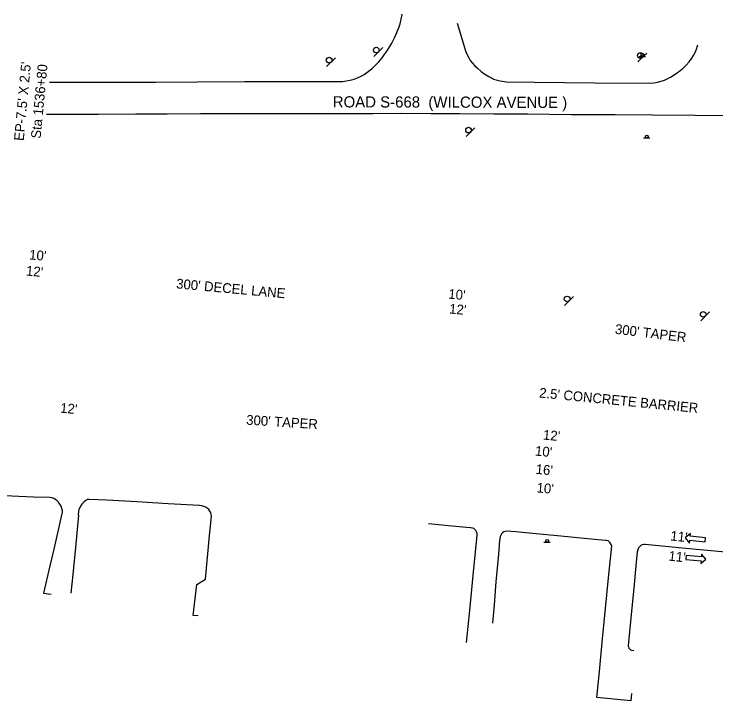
# Model space of a CAD drawing. Extents: x 1800374 to 1802004, y 1187708 to 1188617.
# Drawn here: x 1801167 to 1801669, y 1187839 to 1188331 of the extents above; entities that cross this region are included whole.
import ezdxf

# ---------------------------------------------------------------- set-up
doc = ezdxf.new("R2010")
doc.units = 0
for name, color, linetype in [('RD_EX_Road', 7, 'Continuous'), ('RD_PD_Final_LnLine', 7, 'Continuous'), ('RD_PD_Final_TX', 7, 'Continuous'), ('RD_TX_RoadID', 7, 'Continuous'), ('SN_P_Signs', 7, 'Continuous')]:
    doc.layers.add(name, color=color, linetype=linetype)

# ---------------------------------------------------------------- blocks, each defined once
blk = doc.blocks.new('SARRW2')
at = {"layer": 'RD_PD_Final_LnLine'}
blk.add_lwpolyline([(-12, 1.2), (-12, -1.2), (-2.83, -1.2), (-2.83, -2.83), (0, 0), (-2.83, 2.83), (-2.83, 1.2)], close=True, dxfattribs=at)

msp = doc.modelspace()

# ---------------------------------------------------------------- linework, layer by layer
at = {"layer": 'RD_EX_Road'}
for points in [[(1801192.42, 1188282.25), (1801206.31, 1188282.18), (1801232.85, 1188282.21), (1801268.14, 1188282.24), (1801297.93, 1188282.47), (1801331.99, 1188282.57), (1801366.64, 1188282.73), (1801401.99, 1188282.76), (1801404.75, 1188283.05), (1801407.47, 1188283.57), (1801410.13, 1188284.32), (1801412.72, 1188285.3), (1801415.22, 1188286.49), (1801417.41, 1188287.76), (1801420.28, 1188289.76), (1801423.01, 1188291.94), (1801425.58, 1188294.3), (1801427.99, 1188296.84), (1801430.23, 1188299.53), (1801432.27, 1188302.36), (1801432.65, 1188302.94), (1801435, 1188306.46), (1801437.14, 1188310.11), (1801439.08, 1188313.87), (1801440.81, 1188317.73), (1801442.31, 1188321.68), (1801443.08, 1188324), (1801443.96, 1188327.31), (1801444.61, 1188330.67), (1801444.65, 1188330.92)], [(1801483.98, 1188324.49), (1801489.84, 1188304.69), (1801490.78, 1188302.28), (1801491.93, 1188299.96), (1801493.29, 1188297.76), (1801494.85, 1188295.69), (1801496.59, 1188293.77), (1801498.41, 1188292.09), (1801501.01, 1188289.92), (1801503.75, 1188287.94), (1801506.62, 1188286.15), (1801509.62, 1188284.56), (1801509.89, 1188284.43), (1801514.61, 1188283.24), (1801518.85, 1188282.37), (1801539.13, 1188282.19), (1801582.15, 1188281.81), (1801621.82, 1188281.57), (1801624.47, 1188281.75), (1801627.09, 1188282.15), (1801629.66, 1188282.79), (1801632.16, 1188283.66), (1801634.58, 1188284.75), (1801636.89, 1188286.05), (1801637.9, 1188286.71), (1801640.57, 1188288.35), (1801643.09, 1188290.18), (1801645.48, 1188292.21), (1801647.7, 1188294.4), (1801649.75, 1188296.76), (1801651.61, 1188299.27), (1801652.9, 1188301.27), (1801654.07, 1188303.5), (1801655.02, 1188305.83), (1801655.75, 1188308.24), (1801655.87, 1188308.84)], [(1801750.18, 1188257.47), (1801742.16, 1188257.54), (1801712.17, 1188257.84), (1801684.43, 1188258.15), (1801653.76, 1188258.34), (1801623.47, 1188258.55), (1801596.82, 1188258.7), (1801565.74, 1188258.88), (1801534.34, 1188259.2), (1801510.07, 1188259.36), (1801485.44, 1188259.54), (1801465.11, 1188259.51), (1801443.43, 1188259.67), (1801423.7, 1188259.6), (1801400.14, 1188259.52), (1801374.88, 1188259.49), (1801351.57, 1188259.44), (1801326.73, 1188259.43), (1801300.32, 1188259.52), (1801276.46, 1188259.35), (1801254.13, 1188259.2), (1801227.4, 1188259.14), (1801201, 1188258.95), (1801190.24, 1188258.95)], [(1801201.74, 1187973.73), (1801201.61, 1187975.46), (1801201.23, 1187977.16), (1801200.63, 1187978.8), (1801199.82, 1187980.34), (1801198.89, 1187981.64), (1801197.88, 1187982.69), (1801196.72, 1187983.57), (1801195.43, 1187984.24), (1801194.04, 1187984.7), (1801192.61, 1187984.93), (1801192.55, 1187984.93), (1801181.04, 1187985.29), (1801154.7, 1187986.38), (1801125.59, 1187987.61), (1801124.16, 1187987.2), (1801122.83, 1187986.58), (1801121.6, 1187985.74), (1801120.53, 1187984.73), (1801119.67, 1187983.62), (1801118.69, 1187981.78), (1801117.93, 1187979.84), (1801117.55, 1187978.57)], [(1801298.82, 1187900.38), (1801295.15, 1187900.73), (1801297.8, 1187922.8), (1801303.89, 1187926.72), (1801306.79, 1187957.93), (1801308.15, 1187971.67), (1801308.03, 1187972.96), (1801307.68, 1187974.21), (1801307.11, 1187975.37), (1801306.34, 1187976.42), (1801305.41, 1187977.28), (1801304.13, 1187978.09), (1801302.74, 1187978.69), (1801301.28, 1187979.07), (1801299.77, 1187979.21), (1801299.55, 1187979.21), (1801277.24, 1187980.54), (1801254.75, 1187981.88), (1801233.49, 1187983.09), (1801220.68, 1187983.71), (1801219.58, 1187983.5), (1801218.56, 1187983.05), (1801218.37, 1187982.94), (1801216.91, 1187981.74), (1801215.62, 1187980.37), (1801214.51, 1187978.84), (1801214.22, 1187978.36), (1801213.49, 1187976.29), (1801213.2, 1187975.17), (1801212.93, 1187972.5)], [(1801201.25, 1187973.69), (1801198.94, 1187962.85), (1801195.5, 1187948.11), (1801192.68, 1187936.13), (1801188.03, 1187916.6), (1801193.53, 1187915.92)], [(1801207.97, 1187916.51), (1801209.23, 1187929.92), (1801211.14, 1187949.21), (1801213.43, 1187972.45)], [(1801490.61, 1187881.19), (1801492.94, 1187904.22), (1801495.3, 1187929.3), (1801498.28, 1187958.18), (1801498.16, 1187959.31), (1801497.81, 1187960.39), (1801497.25, 1187961.38), (1801496.61, 1187962.11), (1801495.76, 1187962.75), (1801494.78, 1187963.2), (1801493.74, 1187963.42), (1801493.27, 1187963.44), (1801477.77, 1187964.85), (1801463.3, 1187966.18)], [(1801608.48, 1187844.7), (1801607.98, 1187839.47), (1801583.64, 1187842.04), (1801585.54, 1187860.45), (1801587.79, 1187883.84), (1801590, 1187905.55), (1801592.14, 1187927.65), (1801594.39, 1187950.22), (1801593.91, 1187951.41), (1801593.22, 1187952.5), (1801592.34, 1187953.45), (1801592.29, 1187953.49), (1801591.52, 1187954), (1801590.65, 1187954.3), (1801589.84, 1187954.37), (1801576.98, 1187955.55), (1801557.99, 1187957.37), (1801535.44, 1187959.48), (1801525.81, 1187960.4), (1801519.39, 1187960.98), (1801518.31, 1187960.81), (1801517.29, 1187960.42), (1801516.37, 1187959.82), (1801515.61, 1187959.03), (1801515.03, 1187958.1), (1801514.66, 1187957.07), (1801514.64, 1187956.98), (1801514.26, 1187954.25), (1801513.34, 1187944.4), (1801511.46, 1187924.81), (1801510.29, 1187908.14), (1801509.11, 1187895.02)], [(1801675.84, 1187945.99), (1801644.76, 1187948.86), (1801618.39, 1187951.51), (1801617.31, 1187951.49), (1801616.26, 1187951.23), (1801615.3, 1187950.75), (1801614.46, 1187950.08), (1801613.79, 1187949.23), (1801613.66, 1187949.01), (1801612.69, 1187946.27), (1801611.65, 1187936.09), (1801610.28, 1187920.09), (1801608.41, 1187901.33), (1801606.26, 1187878.96), (1801606.36, 1187878.08), (1801606.69, 1187877.26), (1801607.23, 1187876.55), (1801607.93, 1187876.02), (1801608.44, 1187875.78), (1801610.13, 1187875.62)]]:
    msp.add_lwpolyline(points, dxfattribs=at)
at = {"layer": 'SN_P_Signs'}
for p, q in [((1801424.29, 1188300.51), (1801430.66, 1188306.87)), ((1801613.13, 1188296.62), (1801619.49, 1188302.99)), ((1801390.57, 1188293.34), (1801396.93, 1188299.7)), ((1801614.07, 1188300.62), (1801618.57, 1188300.62)), ((1801490.23, 1188243.25), (1801496.59, 1188249.61)), ((1801617.18, 1188242.3), (1801621.68, 1188242.3)), ((1801560.74, 1188122.48), (1801567.1, 1188128.84)), ((1801658.05, 1188111.44), (1801664.41, 1188117.81)), ((1801545.94, 1187953.06), (1801550.44, 1187953.06))]:
    msp.add_line(p, q, dxfattribs=at)
for centre, radius in [((1801426.06, 1188305.13), 2), ((1801614.89, 1188301.25), 2), ((1801616.33, 1188301.63), 1), ((1801392.33, 1188297.97), 2), ((1801491.99, 1188247.87), 2), ((1801619.44, 1188243.31), 1), ((1801562.5, 1188127.11), 2), ((1801659.81, 1188116.07), 2), ((1801548.2, 1187954.07), 1)]:
    msp.add_circle(centre, radius, dxfattribs=at)

# ---------------------------------------------------------------- block references
at = {"layer": 'RD_PD_Final_LnLine'}
for p, xscale, yscale, rotation in [((1801646.95, 1187956.18), 1.2000000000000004, 1.2000000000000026, 174.6556769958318), ((1801661.75, 1187940.88), 1.2000000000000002, 1.2000000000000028, -5.34432300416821)]:
    msp.add_blockref('SARRW2', p, dxfattribs=dict(at, xscale=xscale, yscale=yscale, rotation=rotation))

# ---------------------------------------------------------------- texts
at = {"layer": 'RD_PD_Final_TX'}
for s, rotation, p in [("10'", 354.7642, (1801177.65, 1188155.41)), ("12'", 354.7642, (1801175.38, 1188143.88)), ("300' DECEL LANE", 354.7642, (1801282.76, 1188134.68)), ("10'", 354.7642, (1801477.34, 1188127.36)), ("12'", 354.7642, (1801477.96, 1188116.74)), ("300' TAPER", 353.1553, (1801596.44, 1188102.22)), ("2.5' CONCRETE BARRIER", 354.4074, (1801542.3, 1188056.63)), ("12'", 354.7642, (1801199.82, 1188045.78)), ("300' TAPER", 356.4156, (1801332.92, 1188037.17)), ("12'", 354.7642, (1801545.02, 1188026.5)), ("10'", 354.7642, (1801539.35, 1188015.04)), ("16'", 354.7642, (1801539.83, 1188002.01)), ("10'", 354.7642, (1801540.45, 1187988.72)), ("11'", 353.9512, (1801636.1, 1187954.36)), ("11'", 353.9512, (1801634.75, 1187939.94))]:
    msp.add_text(s, height=7, rotation=rotation, dxfattribs=at).set_placement(p)
at = {"layer": 'RD_TX_RoadID'}
msp.add_text('ROAD S-668  (WILCOX AVENUE )', height=8, rotation=359.8495, dxfattribs=at).set_placement((1801394.94, 1188264.13))
at = {"layer": 'SN_P_Signs'}
for s, p in [("EP-7.5' X 2.5'", (1801173.95, 1188239.93)), ('Sta 1536+80', (1801186.06, 1188241.56))]:
    msp.add_text(s, height=7, rotation=84.6558, dxfattribs=at).set_placement(p)

doc.saveas('drawing.dxf')
